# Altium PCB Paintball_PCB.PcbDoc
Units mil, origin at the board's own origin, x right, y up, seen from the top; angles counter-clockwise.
Board outline 3540 x 2365 mil, 4 copper layers (L1, Layer 2, Layer 3, Bottom Layer), stack 61.763 mil thick; 55 components, 42 nets, 249 pads, 292 vias.
Unrouted connection lines stored in the file: 13.
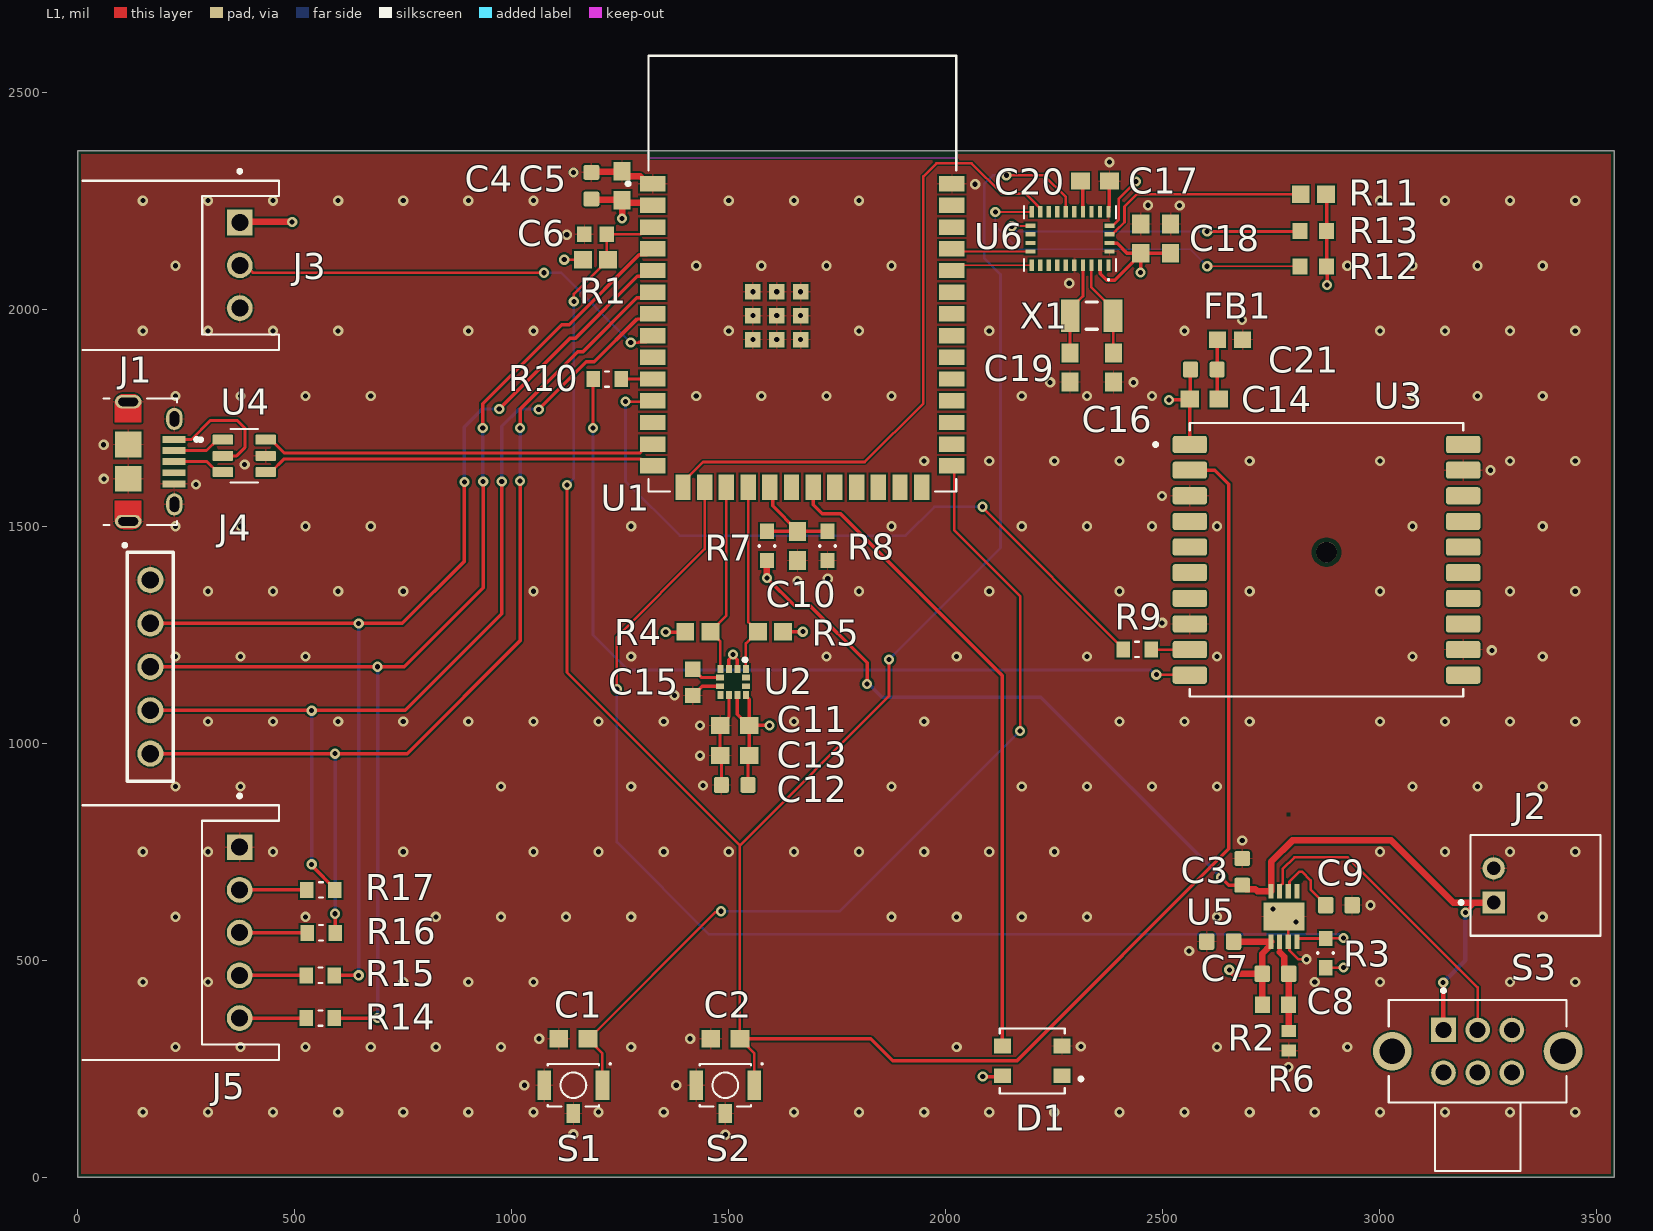
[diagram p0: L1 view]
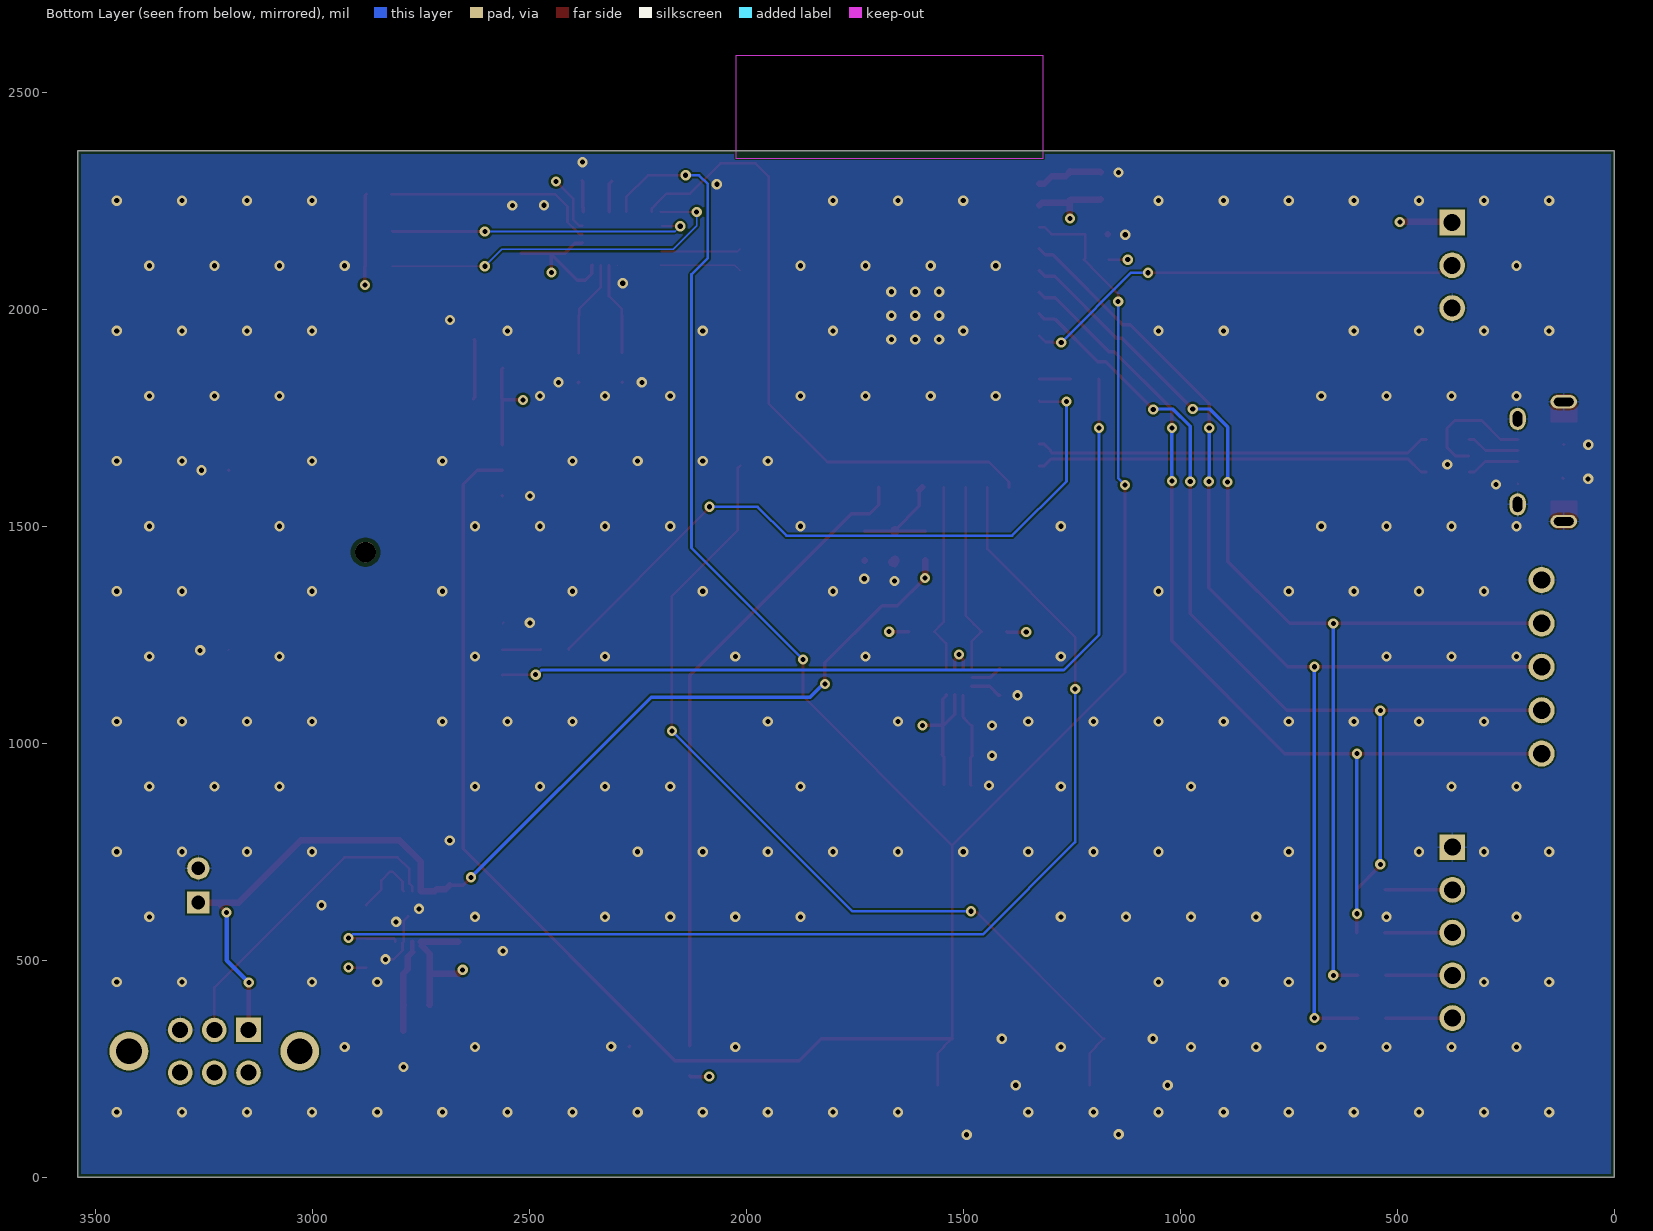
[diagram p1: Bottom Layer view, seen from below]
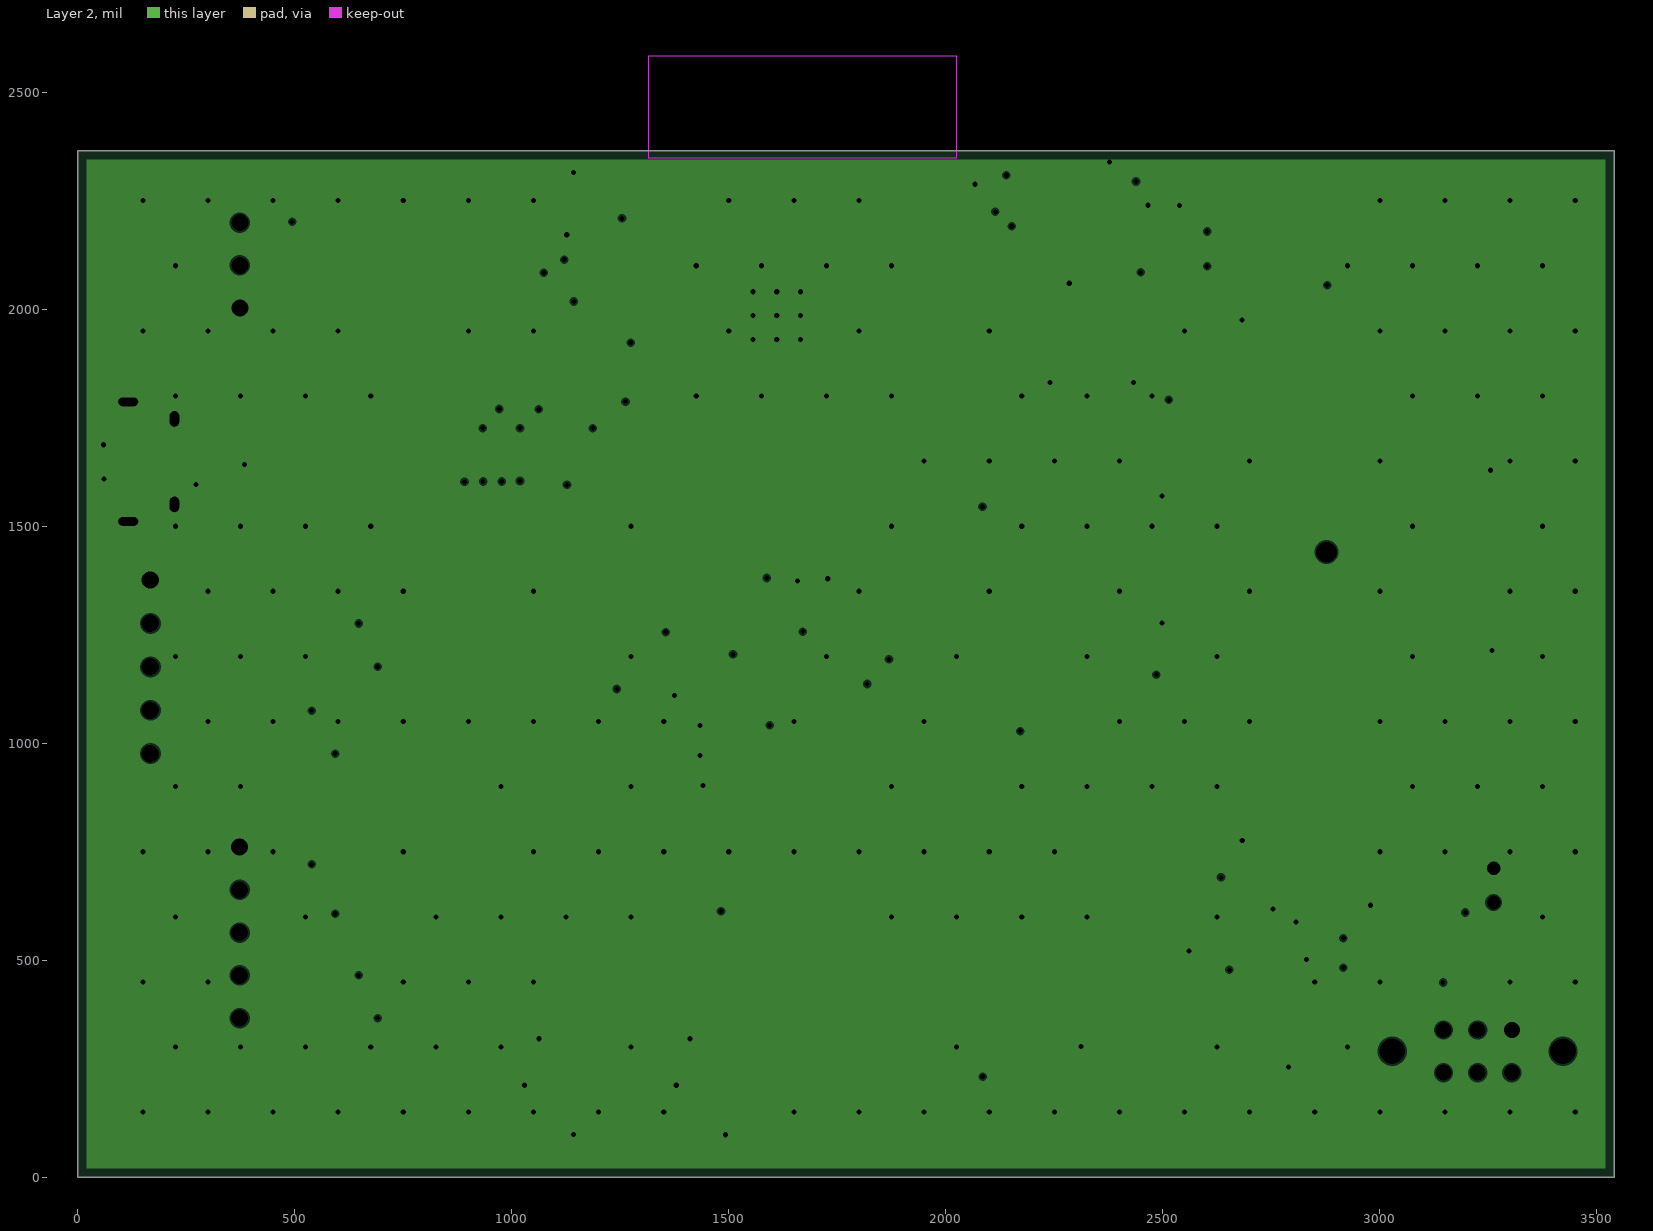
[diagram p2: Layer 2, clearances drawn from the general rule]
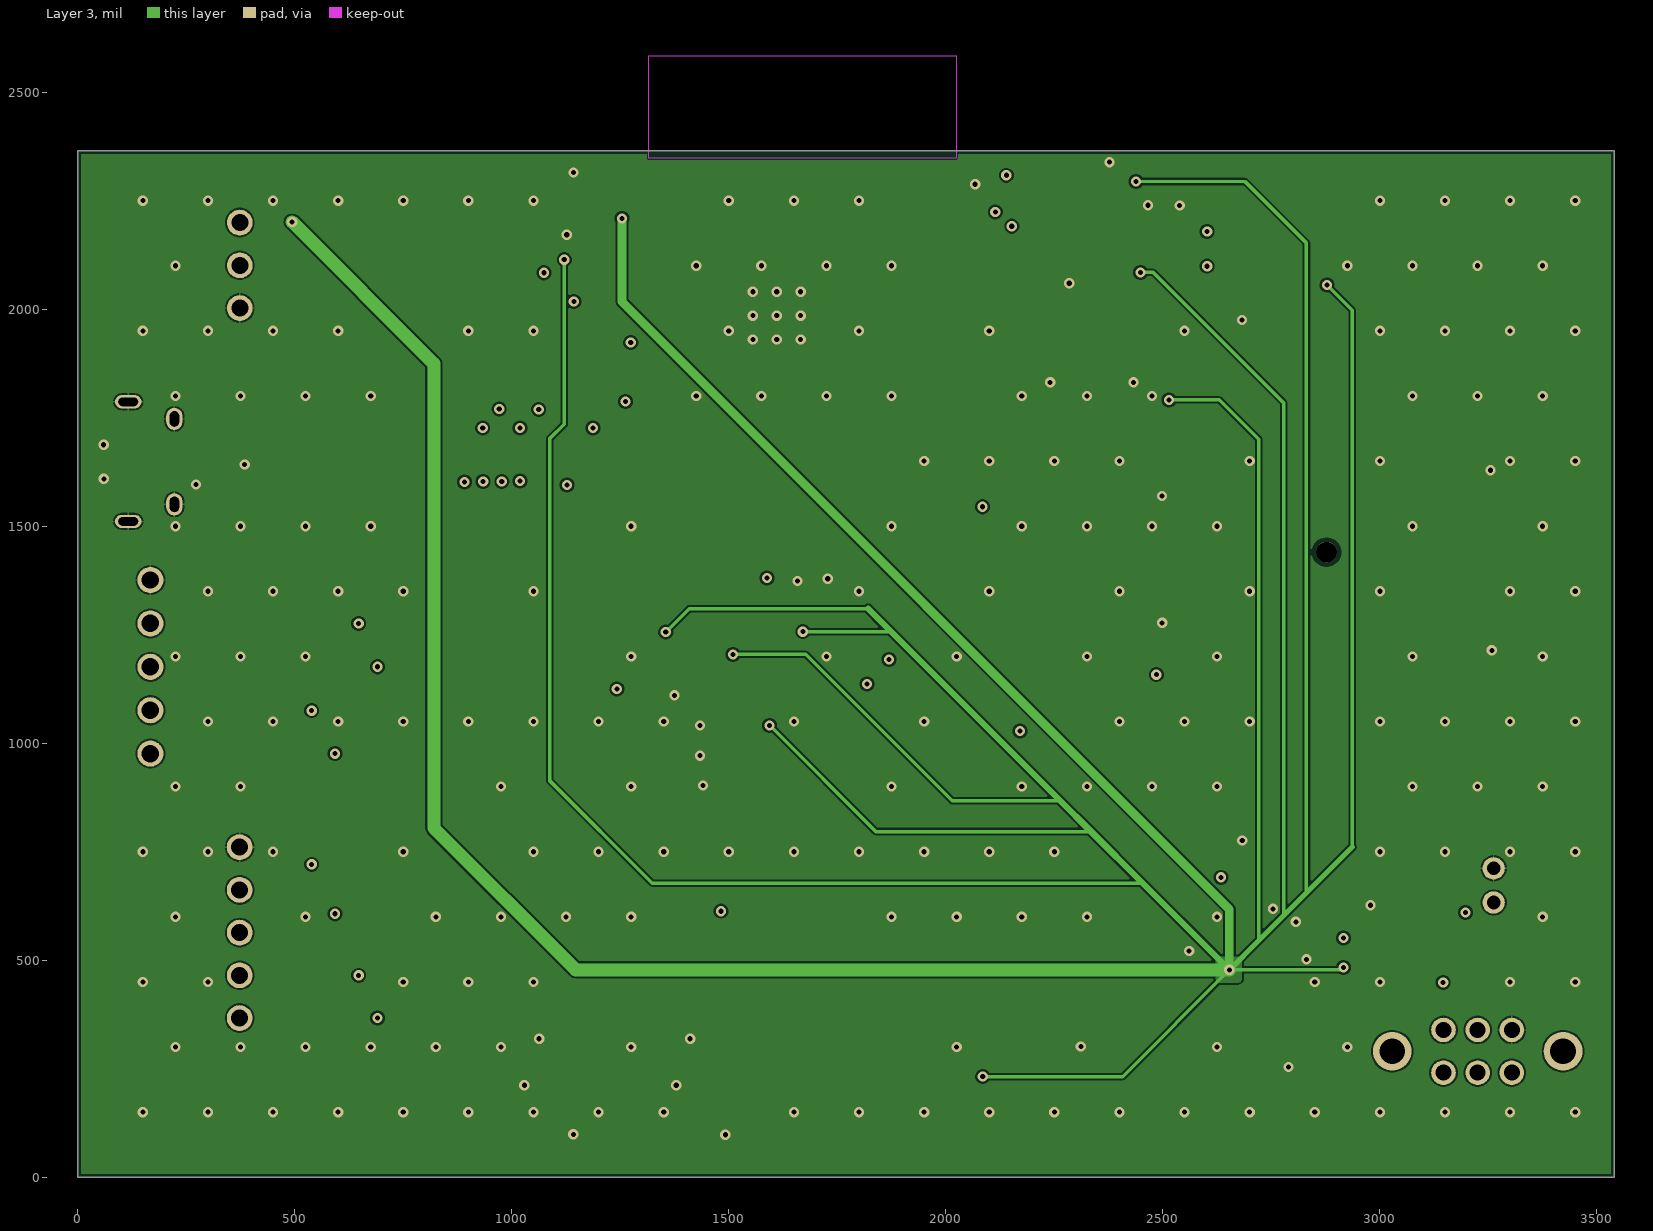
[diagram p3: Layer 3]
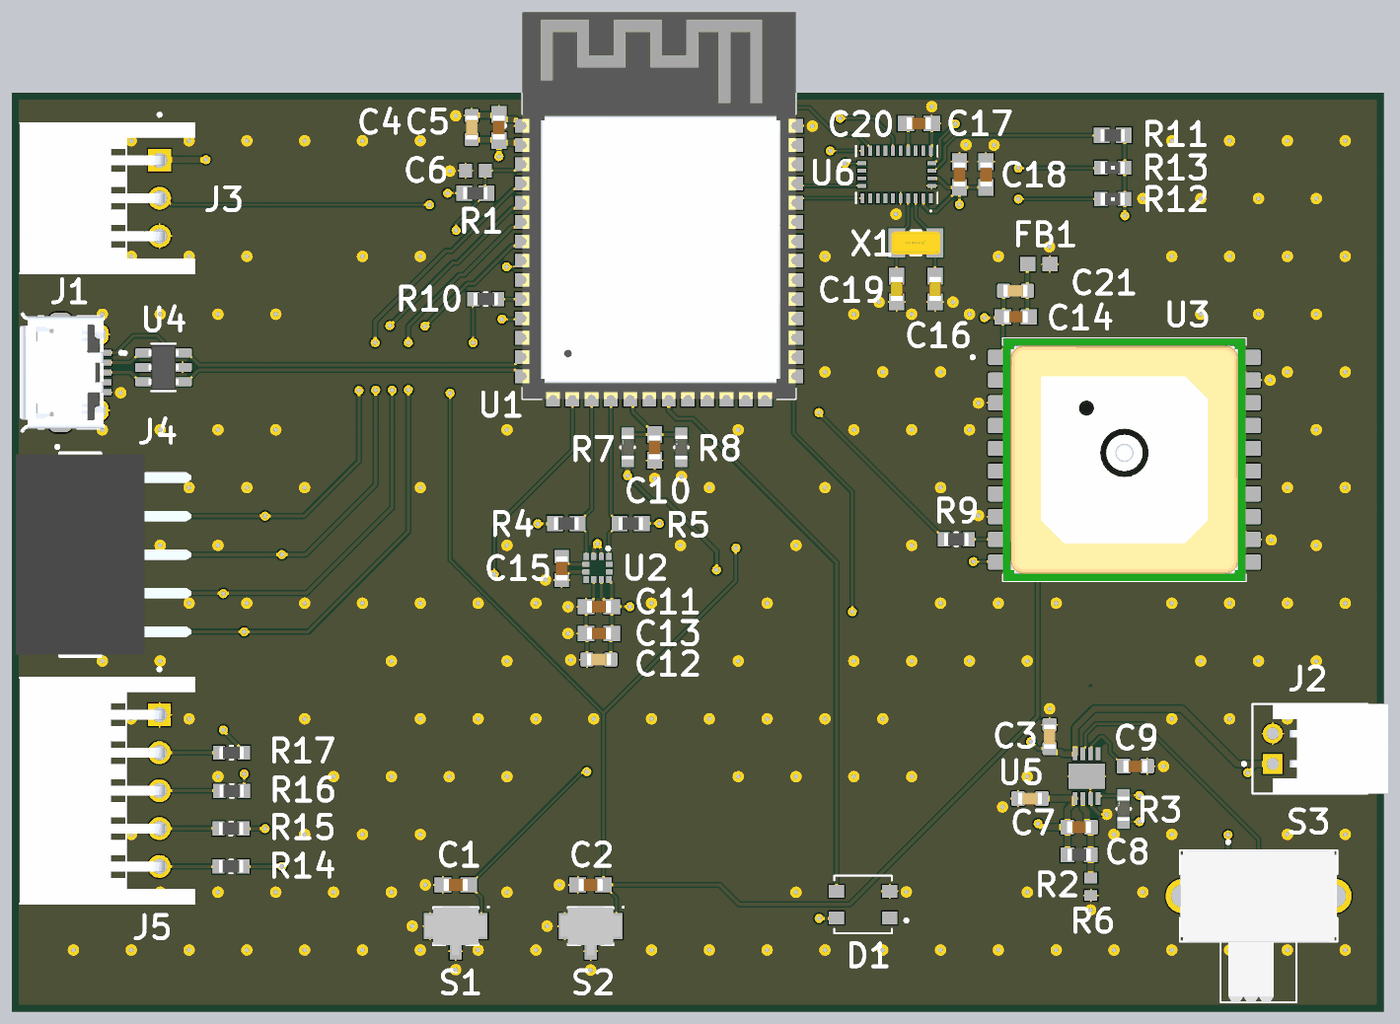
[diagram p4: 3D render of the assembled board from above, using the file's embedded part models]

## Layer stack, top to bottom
Top Solder: solder mask 0.4, Solder Resist, Dk 3.5
L1: signal copper 1.378
Dielectric 2: prepreg 3.913, PP-006, Dk 4.1
Layer 2: plane copper 0.689, net GND
Dielectric 1: dielectric 49.803, FR-4, Dk 4.8
Layer 3: signal copper 0.689
Dielectric 3: prepreg 3.913, PP-006, Dk 4.1
Bottom Layer: signal copper 1.378
Bottom Solder: solder mask 0.4, Solder Resist, Dk 3.5

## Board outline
0,0 3540,0 3540,2365 910,2365 375,2365 175,2365 0,2365

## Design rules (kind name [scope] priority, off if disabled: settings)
BoardOutlineClearance [All] p1: gap=7.87 ignorepadtopadclearanceinfootprint=FALSE
Clearance "Stitching GND" [IsStitchingVia and InNet('GND') vs (IsVia and (Not IsStitchingVia)) Or IsPad] p1: gap=5 ignorepadtopadclearanceinfootprint=FALSE
Clearance [All] p2: gap=4 ignorepadtopadclearanceinfootprint=FALSE except(5: Arc-Via Track-Via SMDPad-Via THPad-Via Via-Via Via-Fill Via-Poly Via-Region Via-Text; 9.84: Arc-Hole Track-Hole SMDPad-Hole THPad-Hole Via-Hole Fill-Hole Poly-Hole Region-Hole Text-Hole)
ComponentClearance [All] p1: gap=4 collisioncheckmode=3 verticalgap=4 showdistances=TRUE
DiffPairsRouting [All] p1: maxlimit=4 minlimit=4 mostfreqgap=4 toplayer_minwidth=4 toplayer_maxwidth=71497.94 toplayer_prefwidth=4 midlayer2_minwidth=4 midlayer2_maxwidth=71497.94 midlayer2_prefwidth=4 bottomlayer_minwidth=4 bottomlayer_maxwidth=71497.94 bottomlayer_prefwidth=4 maxuncoupledlength=500
Height [All] p1: minheight=0 maxheight=71497.94 prefheight=500
HoleSize [All] p1: absolutevalues=TRUE maxlimit=248.03 minlimit=7.87 maxpercent=80.000 minpercent=20.000
HoleToHoleClearance [All] p1: gap=9.84 allowstackedmicrovias=FALSE
MinimumAnnularRing [All] p1: minimumring=3.94
MinimumSolderMaskSliver [All] p1: minsoldermaskwidth=0
PlaneClearance [All] p1: clearance=4
PlaneConnect PlaneConnectPowerPads [InPadClass('PowerPads')] p1: planeconnectstyle=Direct reliefexpansion=20 reliefentries=4 reliefconductorwidth=10 reliefairgap=10
PlaneConnect [All] p2: pad.planeconnectstyle=Relief pad.reliefexpansion=11.81 pad.reliefentries=4 pad.reliefconductorwidth=4 pad.reliefairgap=4 via.planeconnectstyle=Direct via.reliefexpansion=11.81 via.reliefentries=4 via.reliefconductorwidth=5 via.reliefairgap=5
PolygonConnect PolygonConnectPowerPads [All vs (InPadClass('PowerPads'))] p1: connectstyle=Direct reliefconductorwidth=10 reliefentries=4 polygonreliefangle="90 Angle" airgapwidth=10
PolygonConnect [All] p2: thpad.connectstyle=Relief thpad.reliefconductorwidth=4 thpad.reliefentries=4 thpad.polygonreliefangle="90 Angle" thpad.airgapwidth=4 smdpad.connectstyle=Relief smdpad.reliefconductorwidth=4 smdpad.reliefentries=4 smdpad.polygonreliefangle="90 Angle" smdpad.airgapwidth=4 via.connectstyle=Direct via.reliefconductorwidth=5 via.reliefentries=4 via.polygonreliefangle="90 Angle" via.airgapwidth=5
RoutingVias [All] p1: holewidth=7.87 width=17.72 viastyle="Through Hole" minholewidth=7.87 minwidth=17.72 maxholewidth=248.03 maxwidth=257.87
SilkToSilkClearance [All] p1: silktosilkclearance=0
SilkToSolderMaskClearance [IsPad] p1: minsilkscreentomaskgap=4 clearancetoexposedcopper=TRUE
SolderMaskExpansion [All] p1: expansion=2.95 istentingtop=FALSE
SupplyNets "Schematic Supply Nets_2" [InNet('VDD33')] p1: voltage=0.000
SupplyNets "Schematic Supply Nets_1" [InNet('V_BAT')] p2: voltage=0.000
SupplyNets "Schematic Supply Nets" [InNet('GND')] p3: voltage=0.000
Width [All] p1: maxlimit=71497.94 minlimit=4 preferedwidth=4
20 further rules are at their usual default settings.

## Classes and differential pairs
component class Inputs_Power: C1 C2 C3 C4 C5 C6 C7 C8 C9 C10 D1 J1 J2 J3 J4 J5 R1 R2 R3 R6 R7 R8 R14 R15 R16 R17 S1 S2 S3 U4 U5
component class ESP_Sensors: C11 C12 C13 C14 C15 C16 C17 C18 C19 C20 C21 FB1 R4 R5 R9 R10 R11 R12 R13 U2 U3 U6 X1

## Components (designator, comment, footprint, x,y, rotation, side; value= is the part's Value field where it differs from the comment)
C1 "0.1 uF" CAPC1608X90 1141.9,319.07 r0 top
C2 "0.1 uF" CAPC1608X90 1492,319.07 r0 top
C3 "10uF" CAPC1608X90N#1 2683,703.71 r270 top
C4 "10uF" CAPC1608X90N#1 1183.36,2284.46 r270 top
C5 "0.1uF" CAPC1608X90 1254,2284.46 r270 top
C6 "1µF" CAPC1608X90X35LL15T15 1192.9,2172.74 r0 top
C7 "4.7uF" CAPC1608X95N 2632.09,543 r0 top
C8 "10 nF" CAPC1608X90N#2 2759.49,469 r180 top
C9 "10 nF" CAPC1608X90N#2 2905.51,627 r180 top
C10 "0.1uF" CAPC1608X90 1658,1454.46 r90 top
C11 "0.1uF" CAPC1608X90 1513.54,1041 r180 top
C12 "10uF" CAPC1608X90N#1 1513.54,903.91 r180 top
C13 "0.1uF" CAPC1608X90 1513.54,971.4 r180 top
C14 "0.1uF" CAPC1608X90 2595.46,1793 r0 top
C15 "220nF" CAPC1608X90N#3 1417,1140.32 r90 top
C16 "22pF" CAPC1608X90 2386,1865.54 r90 top
C17 "0.1uF" CAPC1608X90 2449,2162.46 r90 top
C18 "0.1uF" CAPC1608X90 2518,2162.46 r90 top
C19 "22pF" CAPC1608X90 2286,1865.54 r90 top
C20 "0.1uF" CAPC1608X90 2343.54,2295 r0 top
C21 "10uF" CAPC1608X90N#1 2594.29,1861 r0 top
D1 "2659" 2659 2199,268 r180 top
FB1 "BLM18RK601SN1D" BEADC1608X95N 2655,1930 r0 top
J1 "10118194-0001LF" AMPHENOL_10118194-0001LF 116.34,1648.77 r270 top
J2 "S2B-PH-K-S(LF)(SN)" JST_S2B-PH-K-S(LF)(SN) 3262,672.37 r90 top
J3 "S3B-XH-A" JST_S3B-XH-A 149,2101 r270 top
J4 "6130XX11821_61300511821" 61300511821 167.32,1176 r270 top
J5 "S5B-XH-A" JST_S5B-XH-A 148.62,563.63 r270 top
R1 "10k" RESC1607X60N 1192.94,2114 r0 top
R2 "11.8k" RESC1508X55N 2759.49,397.08 r180 top
R3 "100k" FP-RC0603-0_55-MFG 2875,516.54 r90 top
R4 "10k" RESC1607X60N 1428.78,1257.02 r0 top
R5 "10k" RESC1607X60N 1596,1257.02 r180 top
R6 "3.74k" RESC1609X50X30LL10T20 2790,314.36 r90 top
R7 "100k" FP-RC0603-0_55-MFG 1587.88,1454.46 r90 top
R8 "100k" FP-RC0603-0_55-MFG 1727.25,1454.46 r90 top
R9 "470" RESC1608X55N#1 2440.72,1216 r0 top
R10 "470" RESC1608X55N#1 1219.72,1839 r180 top
R11 "10k" RESC1607X60N 2846.71,2264.33 r0 top
R12 "CRGCQ0603F2K2" RESC1608X55N#2 2846.71,2098.72 r180 top
R13 "CRGCQ0603F2K2" RESC1608X55N#2 2846.71,2180.19 r180 top
R14 "470" RESC1608X55N#1 558.91,366.78 r0 top
R15 "470" RESC1608X55N#1 558.91,465.2 r0 top
R16 "470" RESC1608X55N#1 560.68,563.1 r0 top
R17 "470" RESC1608X55N#1 560.03,662.05 r0 top
S1 "B3U-1100P" SW_B3U-1100P 1141.9,212 r0 top
S2 "B3U-1100P" SW_B3U-1100P 1492,212 r0 top
S3 "EG2208" SW_EG2208 3225.26,290.21 r0 top
U1 "ESP32-S3-WROOM-1-N8R8" XCVR_ESP32S3WROOM1N8R8 1669.49,2081.91 r0 top
U2 "LSM303AGRTR" LGA12R50P_200X200X100 1509.84,1141.08 r270 top
U3 "CD-PA1616D" XCVR_CD-PA1616D 2877.04,1422.42 r0 top
U4 "USBLC6-2SC6" SOT95P280X145-6N 383.61,1662.08 r0 top
U5 "RTQ2521" RTQ2521 2779,601 r0 top
U6 "BNO086" IC_BNO086 2286.25,2162.48 r180 top
X1 "ABS07-32.768KHZ-T" FP-ABS07-MFG 2335.79,1985 r180 top

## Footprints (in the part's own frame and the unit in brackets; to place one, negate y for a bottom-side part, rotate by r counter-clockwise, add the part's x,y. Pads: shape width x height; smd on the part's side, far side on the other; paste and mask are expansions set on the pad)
2659 [mm]
  rect 1x0.85 smd: 1(-1.75,0.875) 2(-1.75,-0.875) 3(1.75,-0.875) 4(1.75,0.875)
  silkscreen extent -2.95,-1.9 1.9,1.9
61300511821 [mm]
  round 1.53 hole 1.02: 1(-5.08,0) 2(-2.54,0) 3(0,0) 4(2.54,0) 5(5.08,0)
  silkscreen extent -7.21,-1.6 6.7,1.35, body extent -6.6,-4.25 6.6,7.35, height 1.25
AMPHENOL_10118194-0001LF [mm]
  rect 0.4x1.35 smd: 1(-1.3,2.675) 2(-0.65,2.675) 3(0,2.675) 4(0.65,2.675) 5(1.3,2.675)
  oval 0.775x1.55 hole 0.5 slot 1.15 at 90 deg mask+0: SH1(-3.5,0) SH4(3.5,0)
  rect 1.5x1.55 smd: SH2(1,0) SH3(-1,0)
  oval 1.3x0.95 hole 0.55 slot 0.9 at 0 deg: SH5(-2.5,2.7) SH6(2.5,2.7)
  L1 region: -2.3,-0.775 -3.445,-0.775 -3.471,-0.774 -3.497,-0.772 -3.523,-0.769 -3.549,-0.764 -3.574,-0.758 -3.6,-0.751 -3.624,-0.742 -3.648,-0.732 -3.672,-0.721 -3.695,-0.708 -3.717,-0.694 -3.739,-0.68 -3.76,-0.664 -3.78,-0.647 -3.799,-0.629 -3.817,-0.61 -3.834,-0.59 -3.85,-0.569 -3.864,-0.547 -3.878,-0.525 -3.891,-0.502 -3.902,-0.478 -3.912,-0.454 -3.921,-0.43 -3.928,-0.404 -3.934,-0.379 -3.939,-0.353 -3.942,-0.327 -3.944,-0.301 -3.945,-0.275 -3.945,0.275 -3.944,0.301 -3.942,0.327 -3.939,0.353 -3.934,0.379 -3.928,0.404 -3.921,0.43 -3.912,0.454 -3.902,0.478 -3.891,0.502 -3.878,0.525 -3.864,0.547 -3.85,0.569 -3.834,0.59 -3.817,0.61 -3.799,0.629 -3.78,0.647 -3.76,0.664 -3.739,0.68 -3.717,0.694 -3.695,0.708 -3.672,0.721 -3.648,0.732 -3.624,0.742 -3.6,0.751 -3.574,0.758 -3.549,0.764 -3.523,0.769 -3.497,0.772 -3.471,0.774 -3.445,0.775 -2.3,0.775
  L1 region: 3.471,0.774 3.497,0.772 3.523,0.769 3.549,0.764 3.574,0.758 3.6,0.751 3.624,0.742 3.648,0.732 3.672,0.721 3.695,0.708 3.717,0.694 3.739,0.68 3.76,0.664 3.78,0.647 3.799,0.629 3.817,0.61 3.834,0.59 3.85,0.569 3.864,0.547 3.878,0.525 3.891,0.502 3.902,0.478 3.912,0.454 3.921,0.43 3.928,0.404 3.934,0.379 3.939,0.353 3.942,0.327 3.944,0.301 3.945,0.275 3.945,-0.275 3.944,-0.301 3.942,-0.327 3.939,-0.353 3.934,-0.379 3.928,-0.404 3.921,-0.43 3.912,-0.454 3.902,-0.478 3.891,-0.502 3.878,-0.525 3.864,-0.547 3.85,-0.569 3.834,-0.59 3.817,-0.61 3.799,-0.629 3.78,-0.647 3.76,-0.664 3.739,-0.68 3.717,-0.694 3.695,-0.708 3.672,-0.721 3.648,-0.732 3.624,-0.742 3.6,-0.751 3.574,-0.758 3.549,-0.764 3.523,-0.769 3.497,-0.772 3.471,-0.774 3.445,-0.775 2.3,-0.775 2.3,0.775 3.445,0.775
  silkscreen extent -3.7,-1.45 3.7,4.1, body extent -4.02,-2.68 4.02,2.85, height 2.67
BEADC1608X95N [mm]
  rect 1x0.97 smd: 1(-0.735,0) 2(0.735,0)
CAPC1608X90 [mm]
  rect 1.1x1 smd: 1(-0.85,0) 2(0.85,0)
  body extent -0.8,-0.4 0.8,0.4, height 0.95
CAPC1608X90N#1 [mm]
  rrect25% 0.87x0.93 smd: 1(-0.78,0) 2(0.78,0)
  body extent -0.8,-0.4 0.8,0.4, height 0.9
CAPC1608X90N#2 [mm]
  rrect25% 0.92x0.97 smd: 1(-0.775,0) 2(0.775,0)
  body extent -0.8,-0.4 0.8,0.4, height 0.9
CAPC1608X90N#3 [mm]
  rect 0.89x0.93 smd: 1(-0.77,0) 2(0.77,0)
  body extent -0.8,-0.4 0.8,0.4, height 0.9
CAPC1608X90X35LL15T15 [mm] "Chip Capacitor, 2-Leads, Body 1.60x0.81mm, IPC High Density"
  rect 0.85x0.9 smd: 1(-0.65,0) 2(0.65,0)
  body extent -0.88,-0.48 0.87,0.48, height 0.9
CAPC1608X95N [mm]
  rrect25% 0.9x0.97 smd: 1(-0.785,0) 2(0.785,0)
  body extent -0.8,-0.4 0.8,0.4, height 0.95
FP-ABS07-MFG [mm]
  rect 1.1x1.9 smd paste+0 mask+0: 1(-1.25,0) 2(1.25,0)
  silkscreen extent -0.33,-0.8 0.33,0.8, body extent -1.9,-1.05 1.9,1.05, height 0.25
FP-RC0603-0_55-MFG [mm]
  rect 0.9x0.8 smd paste+0 mask+0: 1(-0.85,0) 2(0.85,0)
  silkscreen extent -0.03,-0.45 0.03,0.45, body extent -1.4,-0.55 1.4,0.55, height 0.25
IC_BNO086 [mm]
  rect 0.25x0.675 smd: 1(-2.25,1.562) 6(-2.25,-1.562) 7(-1.75,-1.562) 8(-1.25,-1.562) 9(-0.75,-1.562) 10(-0.25,-1.562) 11(0.25,-1.562) 12(0.75,-1.562) 13(1.25,-1.562) 14(1.75,-1.562) 15(2.25,-1.562) 20(2.25,1.562) 21(1.75,1.562) 22(1.25,1.562) 23(0.75,1.562) 24(0.25,1.562) 25(-0.25,1.562) 26(-0.75,1.562) 27(-1.25,1.562) 28(-1.75,1.562)
  rect 0.575x0.25 smd: 2(-2.312,0.75) 3(-2.312,0.25) 4(-2.312,-0.25) 5(-2.312,-0.75) 16(2.312,-0.75) 17(2.312,-0.25) 18(2.312,0.25) 19(2.312,0.75)
  silkscreen extent -2.69,-1.9 2.69,2.45
JST_S2B-PH-K-S(LF)(SN) [mm]
  rect 1.308x1.308 / inner round 1.308 / far side rect 1.308x1.308 hole 0.8: 1(-1,0)
  round 1.308 hole 0.8: 2(1,0)
  silkscreen extent -2.95,-6.25 2.95,2, body extent -2.95,-7.6 2.95,0, height 4.8
JST_S3B-XH-A [mm]
  rect 1.508x1.508 / inner round 1.508 / far side rect 1.508x1.508 hole 1: 1(-2.5,5.7)
  round 1.508 hole 1: 2(0,5.7) 3(2.5,5.7)
  silkscreen extent -5.6,-3.5 4.95,8, body extent -4.95,-3.5 4.95,8, height 6.1
JST_S5B-XH-A [mm]
  rect 1.508x1.508 / inner round 1.508 / far side rect 1.508x1.508 hole 1: 1(-5,5.7)
  round 1.508 hole 1: 2(-2.5,5.7) 3(0,5.7) 4(2.5,5.7) 5(5,5.7)
  silkscreen extent -8.1,-3.5 7.45,8, body extent -7.45,-3.5 7.45,8, height 6.1
LGA12R50P_200X200X100 [mm]
  rect 0.45x0.35 smd mask+0: 1(-0.76,0.75) 2(-0.76,0.25) 3(-0.76,-0.25) 4(-0.76,-0.75) 7(0.76,-0.75) 8(0.76,-0.25) 9(0.76,0.25) 10(0.76,0.75)
  rect 0.35x0.45 smd mask+0: 5(-0.25,-0.76) 6(0.25,-0.76) 11(0.25,0.76) 12(-0.25,0.76)
  silkscreen extent -1.4,0.6 -1.2,0.8
RESC1508X55N [mm]
  rect 0.9x0.97 smd: 1(-0.76,0) 2(0.76,0)
  body extent -0.77,-0.4 0.77,0.4, height 0.55
RESC1607X60N [mm]
  rect 1.04x1.02 smd: 1(-0.735,0) 2(0.735,0)
  body extent -0.8,-0.4 0.8,0.4, height 0.55
RESC1608X55N#1 [mm]
  rect 0.79x0.93 smd: 1(-0.82,0) 2(0.82,0)
  silkscreen extent -0.11,-0.45 0.11,0.45, body extent -0.8,-0.4 0.8,0.4, height 0.55
RESC1608X55N#2 [mm]
  rect 0.87x0.93 smd: 1(-0.78,0) 2(0.78,0)
  body extent -0.8,-0.4 0.8,0.4, height 0.55
RESC1609X50X30LL10T20 [mm] "Chip Resistor, 2-Leads, Body 1.55x0.85mm, IPC High Density"
  rect 0.7x0.85 smd: 1(-0.575,0) 2(0.575,0)
  body extent -0.82,-0.48 0.82,0.48, height 0.5
RTQ2521 [mm]
  rect 0.3x0.85 smd: 1(-0.756,-1.473) 2(-0.253,-1.473) 3(0.25,-1.473) 4(0.753,-1.473) 5(0.756,1.473) 6(0.253,1.473) 7(-0.25,1.473) 8(-0.753,1.473)
  rect 2.4x1.65 smd: 9(0,0)
SOT95P280X145-6N [mm]
  rrect25% 1.21x0.59 smd: 1(-1.255,0.95) 2(-1.255,0) 3(-1.255,-0.95) 4(1.255,-0.95) 5(1.255,0) 6(1.255,0.95)
  silkscreen extent -2.65,-1.57 0.81,1.57, body extent -1.4,-1.46 1.4,1.46, height 0.4
SW_B3U-1100P [mm]
  rect 0.8x1.7 smd: 1(1.7,0) 2(-1.7,0)
  rect 0.8x1.1 smd: 3(0,-1.65)
  silkscreen extent -1.5,-1.25 2.2,1.3, body extent -2,-1.9 2,1.25, height 1.6
SW_EG2208 [mm]
  rect 1.438x1.438 / inner round 1.438 / far side rect 1.438x1.438 hole 0.93: 1(-2,1.25)
  round 1.438 hole 0.93: 2(0,1.25) 3(2,1.25) 4(-2,-1.25) 5(0,-1.25) 6(2,-1.25)
  round 2.265 hole 1.51: S1(-5,0) S2(5,0)
  silkscreen extent -5.2,-7 5.2,3.65, body extent -5.15,-7 5.15,3, height 5
XCVR_CD-PA1616D [mm]
  rrect25% 2x1 smd: 1(-8,6.75) 2(-8,5.25) 3(-8,3.75) 4(-8,2.25) 5(-8,0.75) 6(-8,-0.75) 7(-8,-2.25) 8(-8,-3.75) 9(-8,-5.25) 10(-8,-6.75) 11(8,-6.75) 12(8,-5.25) 13(8,-3.75) 14(8,-2.25) 15(8,-0.75) 16(8,0.75) 17(8,2.25) 18(8,3.75) 19(8,5.25) 20(8,6.75)
  round 1.21 hole 1.21 unplated: ""(0,0.45)
  silkscreen extent -10.1,-8 8,8, body extent -8,-8 8,8, height 6.7
XCVR_ESP32S3WROOM1N8R8 [mm]
  rect 1.5x0.9 smd: 1(-8.75,5.26) 2(-8.75,3.99) 3(-8.75,2.72) 4(-8.75,1.45) 5(-8.75,0.18) 6(-8.75,-1.09) 7(-8.75,-2.36) 8(-8.75,-3.63) 9(-8.75,-4.9) 10(-8.75,-6.17) 11(-8.75,-7.44) 12(-8.75,-8.71) 13(-8.75,-9.98) 14(-8.75,-11.25) 27(8.75,-11.25) 28(8.75,-9.98) 29(8.75,-8.71) 30(8.75,-7.44) 31(8.75,-6.17) 32(8.75,-4.9) 33(8.75,-3.63) 34(8.75,-2.36) 35(8.75,-1.09) 36(8.75,0.18) 37(8.75,1.45) 38(8.75,2.72) 39(8.75,3.99) 40(8.75,5.26)
  rect 0.9x1.5 smd: 15(-6.985,-12.5) 16(-5.715,-12.5) 17(-4.445,-12.5) 18(-3.175,-12.5) 19(-1.905,-12.5) 20(-0.635,-12.5) 21(0.635,-12.5) 22(1.905,-12.5) 23(3.175,-12.5) 24(4.445,-12.5) 25(5.715,-12.5) 26(6.985,-12.5)
  rect 0.9x0.9 smd: 41_1(-1.5,-2.46) 41_2(-2.9,-2.46) 41_3(-0.1,-2.46) 41_4(-2.9,-3.86) 41_5(-1.5,-3.86) 41_6(-0.1,-3.86) 41_8(-1.5,-1.06) 41_9(-0.1,-1.06)
  rect 0.9x0.9 smd mask+0.075: 41_7(-2.9,-1.06)
  Keep-Out Layer region: 9,6.75 -9,6.75 -9,12.75 9,12.75
  Keep-Out Layer region: 9,6.75 -9,6.75 -9,12.75 9,12.75
  silkscreen extent -10.3,-12.75 9,12.75, body extent -9,-12.75 9,12.75, height 3.25

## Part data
C1 C2 C5 C10 C11 C13 C14 C17 C18 C20: library part C0603C104K5RACTU, "0.1 ÂµF Â±10% 50V Ceramic Capacitor X7R 0603 (1608 Metric)", Package="603-2 KEMET"
C3 C4 C12 C21: library part CL10A106KP8NNNC, "10 ÂµF Â±10% 10V Ceramic Capacitor X5R 0603 (1608 Metric)", Package="SMD-2 Samsung"
C6: library part CMP-2006-02241-1, Manufacturer=Kemet, Part Number=C0603C105K9PACTU
C7: library part CL10B475KQ8NQNC, "4.7 ÂµF Â±10% 6.3V Ceramic Capacitor X7R 0603 (1608 Metric)", Package="SMD-2 Samsung"
C8 C9: library part C0603C103K5RACTU, "10000 pF ±10% 50V Ceramic Capacitor X7R 0603 (1608 Metric)", Package=None
C15: library part GCM188R71H224KA64D, "Multilayer Ceramic Capacitor, AEC-Q200 GCM Series, 0.22 - F, - 10%, X7R, 50 V", Package="1608-2 MURATA"
C16 C19: library part C0603C220J5GACTU, "22pF Â±5% 50V Ceramic Capacitor C0G, NP0 0603 (1608 Metric)", Package="0603 Kemet"
D1: "20 AWG Hook-Up Wire 26/34 White 300V 40.00' _12.19m_", Package="TQFP-32 Adafruit Industries"
FB1: "FERRITE BEAD 600 OHM 0603 1LN", Package=None
J1: "Micro USB, Input Output Connectors, B TYPE RECEPTACLE with flange", Package=None
J2: "Connector Header Through Hole, Right Angle 2 position", Package=None
J3: Package=None
J4: "5 Position Receptacle Connector 0.100 (2.54mm) Through Hole Gold", Package=None
J5: "Connector Header Through Hole, Right Angle 5 position 0.098 (2.50mm)", Package=None
R1 R4 R5 R11: library part RC0603FR-0710KL, "10 kOhms Â±1% 0.1W, 1/10W Chip Resistor 0603 (1608 Metric) Moisture Resistant Thick Film", Package="0603 Yageo"
R2: library part RMCF0603FT11K8, "11.8 kOhms Â±1% 0.1W, 1/10W Chip Resistor 0603 (1608 Metric) Automotive AEC-Q200 Thick Film", Package="1508 Stackpole"
R3 R7 R8: library part CMP-2100-03662-2, "RES SMD 100K OHM 1% 1/10W 0603", Case Code (Imperial)=0603, Case Code (Metric)=1608, Max Operating Temperature=155°C, Max Power Dissipation=100mW, Min Operating Temperature=-55°C, Resistance=100kR, Resistance Tolerance=1%, Resistor Type="Thick Film", Temperature Coefficient=100ppm/°C, Voltage Rating=50V, Working Voltage=75V
R6: library part CMP-2000-03309-1, "3.74 kOhms ±1% 0.125W, 1/8W Chip Resistor 0603 (1608 Metric) Automotive AEC-Q200 Thick Film", Manufacturer="Vishay Dale", Part Number=CRCW06033K74FKEA
R9 R10 R14 R15 R16 R17: library part RC0603JR-07470RL, "470 Ohms Â±5% 0.1W, 1/10W Chip Resistor 0603 (1608 Metric) Moisture Resistant Thick Film", Package="1608 Yageo"
R12 R13: "Fixed Resistor CRGCQ 0603 2K2 1%", Package="1608 Rohm Semiconductor"
S1 S2: "Tactile Switch SPST-NO Top Actuated Surface Mount", Package="Custom Package Omron"
S3: "2P2T Sub-miniature Slide Switch", Package=None
U1: "Bluetooth, WiFi 802.11b/g/n, Bluetooth v5.0 Transceiver Module 2.4GHz PCB Trace Surface Mount", Package=None
U2: "Accelerometer, Magnetometer, Temperature, 6 Axis Sensor IÂ²C, SPI Output", Package="LGA-12 STMicroelectronics"
U3: "CD-PA1616DGNSS patch antenna module", Package=Package
U4: "17V Clamp 5A (8/20Âµs) Ipp Tvs Diode Surface Mount SOT-23-6", Package="SOT-23-6 STMicroelectronics"
U6: "Accelerometer, Gyroscope, Magnetometer, Temperature, 9 Axis Sensor I2C, SPI Output", Package="TFLGA-28 CEVA Technologies, Inc."
X1: library part CMP-0447-00001-4, "Crystal 32.768kHz ±20ppm (Tol) 12.5pF FUND 70kΩ 2-Pin CSMD T/R", Case/Package=CSMD, ESR (Equivalent Series Resistance)=70kR, Frequency=32.768kHz, Frequency Tolerance=20ppm, Load Capacitance=12.5pF, Max Operating Temperature=85°C, Min Operating Temperature=-40°C, Operating Frequency="32.768 kHz", Package Quantity=3000

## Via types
v1: diameter 23.62, hole 11.81, L1 to Bottom Layer, 281 vias
v2: diameter 23.62, hole 11.81, L1 to Bottom Layer, tented top, 11 vias

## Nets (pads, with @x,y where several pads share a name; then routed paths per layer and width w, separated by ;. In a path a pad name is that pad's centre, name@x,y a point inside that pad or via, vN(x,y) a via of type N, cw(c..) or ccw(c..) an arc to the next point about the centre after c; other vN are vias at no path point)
B1: J4.3 R14.2 U1.4 | length 2715.4
  L1 w8: J4.3 752,1176 934,1358 v1(934,1603) ; R14.2 v1(690.78,366.78) ; v1(933,1726) 933,1782 1115.3,1964.3 1132.23,1964.3 1293.21,2125.28 1311.28,2125.28 U1.4
  Bottom Layer w8: v1(690.78,366.78) v1(690.78,1176.22) ; v1(933,1726) 933.5,1725.5 933.5,1603.5 v1(934,1603)
B2: J4.2 R15.2 U1.5 | length 2543
  L1 w8: J4.2 748,1276 891,1419 v1(891,1602) ; R15.2 v1(647.2,465.2) ; v1(971,1770) 1134.48,1933.48 1147.33,1933.48 1289.43,2075.58 1311.58,2075.58 U1.5
  Bottom Layer w8: v1(647.2,465.2) v1(647.2,1275.8) ; v1(891,1602) 890.5,1602.5 890.5,1728.5 932,1770 v1(971,1770)
B3: J4.5 R16.2 U1.6 | length 2323.4
  L1 w8: J4.5 v1(593,976) 759,976 1019,1236 v1(1019,1604) ; R16.2 v1(593,607) ; v1(1019,1726) 1019,1769.42 1151.83,1902.25 1164.16,1902.25 1287.86,2025.96 1311.96,2025.96 U1.6
  Bottom Layer w8: v1(593,607) v1(593,976) ; v1(1019,1604) v1(1019,1726)
B4: J4.4 R17.2 U1.7 | length 2224.8
  L1 w8: J4.4 755,1076 977,1298 v1(977,1603) ; v1(539,721) 540.86,719.14 540.86,716.26 592.31,664.81 R17.2 ; v1(1062,1769) 1172,1879 1190.14,1879 1288.46,1977.32 1313.32,1977.32 U1.7
  Bottom Layer w8: v1(539,721) v1(539,1075) ; v1(977,1603) 977,1730 1017,1770 1061,1770 v1(1062,1769)
EN_LDO: S3.2 U5.7 | length 736.6
  L1 w6: U5.7 2769.16,669.83 2776.06,676.73 2776.06,709.96 2803.31,737.21 2925.63,737.21 3225.26,437.58 S3.2
ENV_SCL: R12.2 U6.15 | length 856.3
  L1 w4: v1(2114,2224) U6.15 ; v1(2602,2099) 2815.72,2099 R12.2
  Bottom Layer w4: v1(2114,2224) 2114,2192 2168,2138 2563,2138 v1(2602,2099)
ENV_SDA: R13.2 U6.16 | length 713.1
  L1 w4: v1(2152,2191) 2152.5,2191.5 2194.7,2191.5 U6.16
  L1 w6: v1(2602,2179) 2814.81,2179 R13.2
  Bottom Layer w4: v1(2152,2191) 2164,2179 v1(2602,2179)
GND: C1.1 C2.1 C3.1 C4.1 C5.1 C6.1 C7.1 C9.1 C10.1 C11.2 C12.2 C13.2 C15.1 C16.1 C17.2 C18.2 C19.1 C20.2 D1.2 FB1.2 J1.5 J1.SH1 J1.SH2 J1.SH3 J1.SH4 J1.SH5 J1.SH6 J2.2 J3.3 J4.1 J5.1 R6.1 R8.1 S1.2 S1.3 S2.2 S2.3 S3.3 U1.1 U1.40 U1.41_1 U1.41_2 U1.41_3 U1.41_4 U1.41_5 U1.41_6 U1.41_7 U1.41_8 U1.41_9 U2.6 U2.8 U3.3 U3.8 U3.12 U3.19 U4.5 U5.3 U5.9 U6.2 U6.6 U6.25 | length 676.4
  L1 w4: U6.25@2296.05,2100.91 U6.25 ; U3.8@2558.86,1278 U3.8 ; U3.12 U3.12@3193.72,1214
  L1 w6: U5.9 2788.84,591.16 U5.3 2791.75,540.09 2791.75,522.71 2812.45,502 v1(2831,502)
  L1 w7: J1.SH3 J1.SH3@116.48,1688 ; J1.SH2@117.32,1609.4 J1.SH2@118.93,1611 ; J1.5 J1.5@221.95,1597.29 ; C13.2@1479.09,970.42 1482.83,966.67 C12.2 C12.2@1481.92,903 ; C13.2@1479.09,972.38 1480.07,973.37 C11.2 ; C13.2@1479.67,971 C13.2 ; C11.2@1482.04,1041 1498.22,1057.19 1498.22,1059.15 1500,1060.93 U2.8
  L1 w8: J4.1@167.16,1376.16 J4.1 ; J5.1 J5.1@373.55,761 ; C15.1@1416,1111 C15.1 ; C15.1@1417.79,1110 1439.02,1131.24 U2.6 ; D1.2 D1.2@2269.35,301 ; C19.1@2285.36,1831.43 C19.1 ; U6.6 2374.83,2232.36 2377,2234.52 C20.2 C20.2@2377.46,2295.46 ; C16.1 C16.1@2387.07,1831 ; U3.3@2562.02,1570 U3.3 ; U3.19 U3.19@3192.11,1629
  L1 w15: J3.3 J3.3@373.85,2003.01 ; v1(1142,2315) v1@1142.09,2315.09 ; C4.1@1183.27,2315.09 1184.73,2316.55 1252.62,2316.55 C5.1 ; C5.1@1254,2315.96 1263.96,2306 1296.19,2306 1313.19,2289 U1.1 ; C10.1@1657.88,1412.11 C10.1@1662.38,1416.62 ; R8.1@1727.03,1420.77 R8.1
  L1 w22: C10.1 C10.1@1662.38,1416.62
  Bottom Layer w8: J2.2@3261.87,711.87 J2.2
  other v1: 1492,98 1141.9,98.9 150,150 300,150 450,150 600,150 750,150 900,150 1050,150 1200,150 1350,150 1650,150 1800,150 1950,150 2100,150 2250,150 2400,150 2550,150 2700,150 2850,150 3000,150 3150,150 3300,150 3450,150 1029,212 1379,212 2789.45,253.82 225,300 375,300 525,300 675,300 825,300 975,300 1275,300 2025,300 2625,300 2925,300 2311,301 1063.07,319.07 1410.93,319.07 150,450 300,450 750,450 900,450 1050,450 2850,450 3000,450 3300,450 3450,450 2560.65,521.13 225,600 525,600 825,600 975,600 1125,600 1275,600 1875,600 2025,600 2175,600 2325,600 2625,600 3375,600 2978.58,626.66 150,750 300,750 450,750 750,750 1050,750 1200,750 1350,750 1500,750 1650,750 1800,750 1950,750 2100,750 2250,750 3000,750 3150,750 3300,750 3450,750 2683,776 225,900 375,900 975,900 1275,900 1875,900 2175,900 2325,900 2475,900 2625,900 3075,900 3225,900 3375,900 1440.4,902.58 1433.4,971.36 1433.64,1040.85 300,1050 450,1050 600,1050 750,1050 900,1050 1050,1050 1200,1050 1350,1050 1650,1050 1950,1050 2400,1050 2550,1050 2700,1050 3000,1050 3150,1050 3300,1050 3450,1050 1374.98,1110.28 225,1200 375,1200 525,1200 1275,1200 1725,1200 2025,1200 2325,1200 2625,1200 3075,1200 3375,1200 3258,1214 2498.44,1277.32 300,1350 450,1350 600,1350 750,1350 1050,1350 1800,1350 2100,1350 2400,1350 2700,1350 3000,1350 3300,1350 3450,1350 1658.09,1373.85 1727.94,1378.79 225,1500 375,1500 525,1500 675,1500 1275,1500 1875,1500 2175,1500 2325,1500 2475,1500 2625,1500 3075,1500 3375,1500 2498.07,1569.51 272.6,1596.13 60.23,1609.14 3255,1629 384.62,1642.12 1950,1650 2100,1650 2250,1650 2400,1650 2700,1650 3000,1650 3300,1650 3450,1650 59.76,1687.73 225,1800 375,1800 525,1800 675,1800 1425,1800 1575,1800 1725,1800 1875,1800 2175,1800 2325,1800 2475,1800 3075,1800 3225,1800 3375,1800 2240.37,1831.43 2432.16,1831.37 150,1950 300,1950 450,1950 600,1950 900,1950 1050,1950 1500,1950 1800,1950 2100,1950 2550,1950 3000,1950 3150,1950 3300,1950 3450,1950 2682.54,1974.85 2284.34,2059.7 225,2100 1425,2100 1575,2100 1725,2100 1875,2100 2925,2100 3075,2100 3225,2100 3375,2100 1126.68,2171.45 2466.01,2239.49 2538.7,2238.66 150,2250 300,2250 450,2250 600,2250 750,2250 900,2250 1050,2250 1500,2250 1650,2250 1800,2250 3000,2250 3150,2250 3300,2250 3450,2250 2067.51,2287.89 2377.32,2338.73
  other v2: 2806.36,588.43 2753.74,618.36 1555.32,1929.94 1610.43,1929.94 1665.55,1929.94 1555.32,1985.06 1610.43,1985.06 1665.55,1985.06 1555.32,2040.18 1610.43,2040.18 1665.55,2040.18
H_INTN: U1.15 U6.14 | length 1496.6
  L1 w6: U1.15 1394.49,1601.6 1440.89,1648 1813,1648 1948,1783 1948,2306 1978,2336 2059.36,2336 2129.42,2265.94 2183.83,2265.94 2209.73,2240.04 2209.73,2239.98 2217.35,2232.36 U6.14
NetC1_2: C1.2 S1.1 U1.27 | length 2085.4
  L1 w6: C1.2 C1.2@1177.34,319.07 ; S1.1 1208.83,285.6 1194.02,300.42 1194.02,302.38 C1.2@1177.34,319.07 ; v1(1482,613) 1479.76,610.76 1469.03,610.76 C1.2@1177.34,319.07 ; U1.27 2019,1633.98 2019,1491 2171,1339 v1(2171,1028)
  Bottom Layer w6: v1(1482,613) 1756,613 v1(2171,1028)
NetC8_1: C8.1 R2.1 R6.2 U5.2 | length 215.2
  L1 w10: 2769.03,518.47 U5.2
  L1 w15: 2769.03,518.47 2779.39,508.11 2779.39,479.61 C8.1 2789.7,468.7 2789.7,397.37 R2.1 2789.7,396.78 2789.7,337.3 R6.2
NetC9_2: C9.2 U5.6 | length 161
  L1 w6: U5.6 2791.87,661.91 2791.87,681.25 2814.63,704 2820.43,704 2840.42,684 2840.42,662.56 2875,627.98 C9.2
NetC10_2: C10.2 R7.2 R8.2 U1.19 | length 267.5
  L1 w8: R7.2 C10.2 R8.2 ; U1.19@1601.2,1583.07 1601.2,1546.69 C10.2@1658,1489.9
  L1 w15: U1.19 U1.19@1601.2,1583.07
  L1 w22: C10.2 C10.2@1658,1489.9
NetC14_2: C14.2 C21.2 FB1.1 | length 139.1
  L1 w8: FB1.1 2625,1928.94 C21.2 2625,1796.93 C14.2
NetC15_2: C15.2 U2.5 | length 73.5
  L1 w7: C15.2@1415.63,1172 C15.2 ; C15.2@1416.87,1171.55 1437.5,1150.92 U2.5
NetC16_2: C16.2 U6.27 X1.1 | length 222.9
  L1 w6: U6.27 2335.46,2050.29 2385,2000.75 X1.1 2386,1984 C16.2
NetC19_2: C19.2 U6.26 X1.2 | length 214.4
  L1 w4: X1.2@2286,1984.43 X1.2 ; U6.26 U6.26@2315.92,2100.82
  L1 w6: C19.2 X1.2@2286,1984.43 ; X1.2 2286.57,2000.75 2315.92,2030.1 U6.26@2315.92,2100.82
NetC20_1: C20.1 U6.9 | length 73.4
  L1 w8: C20.1 2315.78,2289.29 U6.9
NetD1_3: D1.3 U1.21 | length 1492.3
  L1 w8: U1.21 1694.49,1549.61 1715.53,1528.57 1757.43,1528.57 2130.1,1155.9 D1.3
NetJ1_1: J1.1 U4.2 | length 292.7
  L1 w7: J1.1 261.95,1699.95 306,1744 367,1744 385,1726 385,1681 366.08,1662.08 U4.2
NetJ1_2: J1.2 U4.1 | length 123
  L1 w7: J1.2 296.88,1674.36 322,1699.48 U4.1
NetJ1_3: J1.3 U4.3 | length 122.5
  L1 w7: J1.3 297.91,1648.77 322,1624.68 U4.3
NetJ3_2: J3.2 U1.8 | length 1031.9
  L1 w6: J3.2 386.61,2101 403.61,2084 v1(1074,2084) ; v1(1274,1923) 1291.86,1923 1293.14,1924.28 1310.28,1924.28 U1.8
  Bottom Layer w6: v1(1074,2084) 1113,2084 v1(1274,1923)
NetJ5_2: J5.2 R17.1 | length 154.7
  L1 w8: J5.2 R17.1
NetJ5_3: J5.3 R16.1 | length 155.6
  L1 w8: J5.3 527.87,563.63 R16.1
NetJ5_4: J5.4 R15.1 | length 153.6
  L1 w8: J5.4 R15.1
NetJ5_5: J5.5 R14.1 | length 153.6
  L1 w8: J5.5 R14.1
NetR3_2: R3.2 U1.16 U5.4 | length 2780.3
  L1 w6: v1(1242,1125) 1242,1244.47 1444.49,1446.96 U1.16 ; U5.4 2808.65,547.09 2811.56,550 R3.2 2876,551 v1(2916,551)
  Bottom Layer w6: v1(1242,1125) 1242,772 1454.41,559.59 2906.63,559.59 2915.22,551 v1(2916,551)
NetR9_2: R9.2 U3.9 | length 89.2
  L1 w6: R9.2 2473.28,1215.72 U3.9
NetR10_2: R10.2 U3.10 | length 2003
  L1 w6: v1(1187,1726) 1187,1838.57 R10.2 ; v1(2485,1158) 2560.75,1158 U3.10
  Bottom Layer w6: v1(1187,1726) 1187,1249.86 1268.11,1168.75 2471.88,1168.75 2482.63,1158 v1(2485,1158)
NetR11_1: R11.1 U6.4 | length 499.7
  L1 w6: U6.4 2383.69,2172.32 2391.31,2179.94 2391.37,2179.94 2411.68,2200.25 2411.68,2236.29 2439.71,2264.33 R11.1
NetU1_13: U1.13 U4.6 | length 914.8
  L1 w7: U4.6 445.23,1699.48 476.34,1668.37 1294.87,1668.37 1298.97,1672.47 1298.97,1674.78 1313.19,1689 U1.13
NetU1_14: U1.14 U4.4 | length 911.3
  L1 w7: U4.4 445.23,1624.68 475.75,1655.2 1296.99,1655.2 1313.19,1639 U1.14
Reset: C2.2 C6.2 R1.2 S2.1 U1.3 U3.2 U6.11 | length 6625.9
  L1 w6: v1(1127.2,1595.11) 1127.2,1162.98 1525.46,764.72 ; v1(1142.99,2017.75) 1142.99,2035.12 1204.4,2096.53 1204.4,2096.92 1221.48,2114 R1.2 1218.49,2117.38 C6.2 1296.93,2172.74 1313.19,2189 U1.3 ; C2.2 1525.46,764.72 ; C2.2@1527.43,319.07 1544.12,302.38 1544.12,300.42 1558.93,285.6 S2.1 ; v1(1869,1193) 1869,1108.25 1525.46,764.72 ; v1(2139.35,2308.38) 2226.62,2308.38 2276.41,2258.59 U6.11
  L1 w8: C2.2 1827.43,319.07 1878.06,268.45 2164.01,268.45 2652,756.44 2652,1597 2619.89,1629.11 U3.2
  Bottom Layer w6: v1(1127.2,1595.11) 1142.99,1610.9 v1(1142.99,2017.75) ; v1(1869,1193) 2126,1450 2126,2080 2088.21,2117.79 2088.21,2288.21 2108.38,2308.38 v1(2139.35,2308.38)
RXD0: U1.36 U6.20 | length 188.6
  L1 w4: U1.36 2025.94,2100.96 U6.20
RXD1: R9.1 U1.11 | length 1612.6
  L1 w6: v1(1262,1787) 1323,1787 U1.11 ; v1(2084.37,1544.72) 2084.37,1542.82 2408.43,1218.76 R9.1
  Bottom Layer w6: v1(1262,1787) 1262,1603 1387,1478 1907,1478 1973.72,1544.72 v1(2084.37,1544.72)
SCL: R5.2 U1.18 U2.1 | length 439.7
  L1 w6: U2.1 1539.37,1229.72 R5.2@1566.67,1257.02 ; U1.18 1544.49,1279.6 1549.59,1274.5 1549.59,1274.1 R5.2@1566.67,1257.02 ; R5.2 R5.2@1566.67,1257.02
SDA: R4.2 U1.17 U2.4 | length 443.4
  L1 w6: R4.2 R4.2@1458.11,1257.02 ; U2.4 1480.31,1234.82 R4.2@1458.11,1257.02 ; U1.17 1494.49,1293.79 1475.19,1274.5 1475.19,1274.1 R4.2@1458.11,1257.02
TXD0: U1.37 U6.19 | length 183.7
  L1 w4: U1.37 2020.03,2132.95 U6.19
TXD1: R10.1 U1.10 | length 73
  L1 w6: R10.1 U1.10
V_BAT: C3.2 J2.1 R7.1 S3.1 U5.8 | length 2514.7
  L1 w8: v1(1587.83,1380.72) 1651.55,1317 1687,1317 1819,1185 1819,1136.86 v1(1818.5,1136.36) ; v1(2634,691) 2652,673 C3.2
  L1 w10: v1(3145.84,448.71) 3145.84,340.11 S3.1 ; v1(3197,610) 3220,633
  L1 w15: v1@1587.86,1380.75 R7.1 ; C3.2 2692.63,663.37 2713.38,663.37 2717.75,659 U5.8 2749.35,726.89 2798.45,776 3026.12,776 3169.12,633 3220,633 J2.1
  Bottom Layer w8: v1(1818.5,1136.36) 1822.73,1136.36 1852.9,1106.19 2218.81,1106.19 v1(2634,691)
  Bottom Layer w10: v1(3145.84,448.71) 3197,499.87 v1(3197,610)
VDD33: C4.2 C5.2 C7.2 C8.2 C11.1 C12.1 C13.1 C14.1 C17.1 C18.1 C21.1 D1.4 J3.1 R1.1 R2.2 R3.1 R4.1 R5.1 R11.2 R12.1 R13.1 U1.2 U2.2 U2.3 U2.9 U2.10 U3.1 U5.1 U6.3 U6.5 U6.28 | length 21890.5
  L1 w6: v1(1121,2114) R1.1 ; U6.5 2383.69,2192 2398.73,2207.04 2398.73,2254.63 v1(2438.23,2294.14) ; R3.1 2875.07,483 v1(2916,483)
  L1 w8: v1(1354.72,1256.02) 1398.45,1256.02 R4.1@1399.45,1257.02 ; R4.1 R4.1@1400.24,1257.02 ; U2.3 1500,1192.38 v1@1509.61,1201.99 ; v1(1509.61,1204.62) v1@1509.61,1201.99 ; U2.9 1519.68,1066.35 1545.03,1041 C11.1 ; U2.2 1519.68,1191.92 v1@1509.61,1201.99 ; U2.10 1539.37,1109.19 1547,1101.56 C11.1 ; C12.1 1544.24,968.64 C13.1 ; C13.1@1548.6,973 C13.1 ; v1(1594,1041) C11.1 ; R5.1 v1(1670.62,1257.02) ; v1(2085,232) 2128.55,232 D1.4 ; U6.28 2356.07,2100.04 2356.07,2081.93 2371,2067 2388.97,2067 C17.1@2448.76,2126.8 ; U6.3 2378.21,2151.71 2394.6,2151.71 2417.31,2129 C17.1 ; v1(2448.76,2084.64) C17.1@2448.76,2126.8 ; v1(2514,1791) 2560.16,1791 2562.08,1792.92 U3.1 ; C18.1 C17.1 ; C21.1@2561,1863.58 C21.1 2563.58,1794.58 C14.1 ; R11.2 2877.42,2262.56 R13.1 R12.1 2878.34,2097.79 v1(2878.34,2055.53) ; C13.1 C11.1 ; C17.1@2448.76,2126.8 2448.76,2128.76 C17.1 ; C17.1@2448.76,2126.8 2449,2127.03 C17.1
  L1 w15: J3.1 374.98,2201 v1(494,2201) ; C4.2 1184.73,2252.38 1252.62,2252.38 1260,2245 1319,2245 U1.2 ; v1(1254,2209) C5.2@1254,2245 ; v1(2653.23,477.83) 2653.97,477.83 2662.8,469 C8.2 ; C7.2 U5.1 ; R2.2 2729.27,397.37 2729.27,468.7 C8.2 ; U5.1@2747.63,533.77 2728.98,515.12 C8.2
  Layer 3 w8: v1(1121,2114) 1121,1735 1087,1701 1087,914 1323.47,677.53 2453.53,677.53 ; v1(1354.72,1256.02) 1408.69,1310 1821.07,1310 ; v1(1509.61,1204.62) 1677.38,1204.62 2014.57,867.43 2263.64,867.43 ; v1(1594,1041) 1838.47,796.53 2334.53,796.53 ; v1(1670.62,1257.02) 1874.04,1257.02 ; v1(2085,232) 2407.4,232 v1(2653.23,477.83) 2910.83,477.83 ccw(c2910.83,483) v1(2916,483) ; v1(2438.23,2294.14) 2689.18,2294.14 2830.85,2152.46 2830.85,655.45 ; v1(2448.76,2084.64) 2477.36,2084.64 2778.09,1783.91 2778.09,602.69 ; v1(2514,1791) 2630.31,1791 2721.36,1699.96 2721.36,545.96 ; v1(2878.34,2055.53) 2936.15,1997.72 2936.15,760.75
  Layer 3 w12: v1(2653.23,477.83) 2721.36,545.96 2778.09,602.69 2830.85,655.45 2936.15,760.75
  Layer 3 w15: 1821.07,1310 1874.04,1257.02 2263.64,867.43 2334.53,796.53 2453.53,677.53 v1(2653.23,477.83)
  Layer 3 w20: v1(1254,2209) 1254,2017 2653.23,617.77 v1(2653.23,477.83)
  Layer 3 w30: v1(494,2201) 820.5,1874.5 820.5,804.5 1147,478 2653.07,478 v1(2653.23,477.83)
pads on no net: D1.1 J1.4 S3.4 S3.5 S3.6 S3.S1 S3.S2 U1.9 U1.12 U1.20 U1.22 U1.23 U1.24 U1.25 U1.26 U1.28 U1.29 U1.30 U1.31 U1.32 U1.33 U1.34 U1.35 U1.38 U1.39 U2.7 U2.11 U2.12 U3. U3.4 U3.5 U3.6 U3.7 U3.11 U3.13 U3.14 U3.15 U3.16 U3.17 U3.18 U3.20 U5.5 U6.1 U6.7 U6.8 U6.10 U6.12 U6.13 U6.17 U6.18 U6.21 U6.22 U6.23 U6.24

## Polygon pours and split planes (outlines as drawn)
GND on Layer 3 "GND_L03_P003" (solid, pour order 3): 0,2365 3540,2365 3540,0 0,0
VDD33 on Layer 3 "VDD33_L03_P000" (solid, pour order 0): 2632.04,508.41 2632.04,508.34 cw(c2672.31,498.34) 2682.31,498.34 2682.31,458.34 cw(c2672.31,458.34) 2672.31,448.34 2632.31,448.34 cw(c2632.31,458.34) 2622.31,458.34 2622.31,498.34 cw(c2632.31,498.34) 2632.31,508.34
GND on Bottom Layer "GND_L04_P004" (solid, pour order 4): 0,2365 3540,2365 3540,0 0,0
GND on L1 "GND_L01_P002" (solid, pour order 2): 0,2365 3540,2365 3540,0 0,0
GND on Layer 2 (split plane): 3519.9,20.1 20.1,20.1 20.1,2344.9 3519.9,2344.9

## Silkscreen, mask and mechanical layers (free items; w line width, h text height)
Board Shape:
  lines w20: 0,0 3540,0 3540,2365 0,2365 0,0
